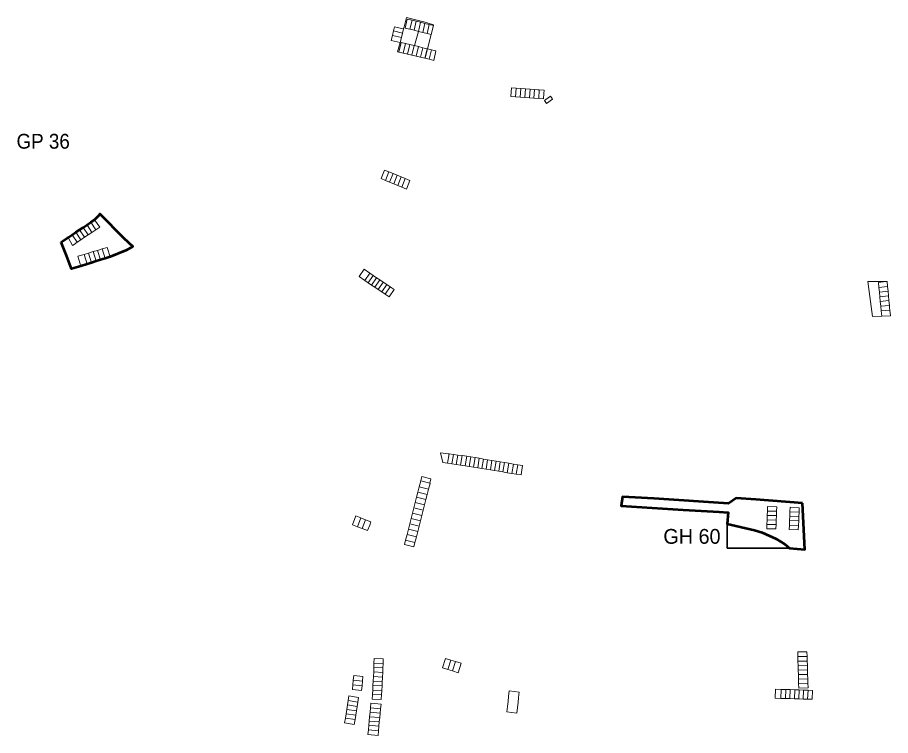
# Model space of a CAD drawing. Extents: x -648438 to -645379, y -1072966 to -1066997.
# Drawn here: x -646934 to -646344, y -1071165 to -1070679 of the extents above; entities that cross this region are included whole.
import ezdxf

# ---------------------------------------------------------------- set-up
doc = ezdxf.new("R2010")
doc.units = 0
doc.header["$LTSCALE"] = 4
doc.layers.add('40', color=7, linetype='Continuous', lineweight=13)
doc.layers.add('60', color=7, linetype='Continuous', lineweight=53)
doc.layers.add('56', color=7, linetype='Continuous')

msp = doc.modelspace()

# ---------------------------------------------------------------- linework, layer by layer
at = {"layer": '40'}
for points in [[(-646677.35, -1070702.69), (-646675.73, -1070696.39), (-646674.86, -1070693), (-646674.11, -1070690.05), (-646673.39, -1070687.24), (-646673.24, -1070686.66), (-646671.4, -1070679.49), (-646659.58, -1070682.49), (-646653.11, -1070684.4), (-646653.22, -1070684.87), (-646655.99, -1070684.19), (-646658.95, -1070683.47), (-646661.87, -1070682.76), (-646664.73, -1070682.06), (-646667.6, -1070681.36), (-646670.86, -1070680.56), (-646672.35, -1070686.63), (-646669.06, -1070687.45), (-646666.2, -1070688.16), (-646663.34, -1070688.87), (-646666.02, -1070698.52), (-646666.17, -1070698.49), (-646669.09, -1070697.79), (-646672, -1070697.09), (-646675.08, -1070696.34), (-646676.65, -1070702.85)], [(-646672.35, -1070686.63), (-646670.86, -1070680.56), (-646667.6, -1070681.36), (-646669.06, -1070687.45)], [(-646669.06, -1070687.45), (-646667.6, -1070681.36), (-646664.73, -1070682.06), (-646666.2, -1070688.16)], [(-646666.2, -1070688.16), (-646664.73, -1070682.06), (-646661.87, -1070682.76), (-646663.34, -1070688.87)], [(-646680.1, -1070688.63), (-646679.41, -1070685.78), (-646673.63, -1070687.18), (-646673.48, -1070686.59), (-646673.24, -1070686.66), (-646673.39, -1070687.24), (-646674.11, -1070690.05)], [(-646663.34, -1070688.87), (-646661.87, -1070682.76), (-646658.95, -1070683.47), (-646660.43, -1070689.59)], [(-646660.43, -1070689.59), (-646658.95, -1070683.47), (-646655.99, -1070684.19), (-646657.47, -1070690.33)], [(-646657.47, -1070690.33), (-646655.99, -1070684.19), (-646653.22, -1070684.87), (-646654.7, -1070691.02)], [(-646681.63, -1070694.97), (-646680.81, -1070691.57), (-646674.86, -1070693), (-646675.73, -1070696.39)], [(-646680.81, -1070691.57), (-646680.1, -1070688.63), (-646674.11, -1070690.05), (-646674.86, -1070693)], [(-646666.02, -1070698.52), (-646663.34, -1070688.87), (-646660.43, -1070689.59), (-646657.47, -1070690.33), (-646654.7, -1070691.02), (-646657.18, -1070700.66), (-646657.42, -1070700.6), (-646660.34, -1070699.9), (-646663.26, -1070699.19)], [(-646676.65, -1070702.85), (-646675.08, -1070696.34), (-646672, -1070697.09), (-646673.57, -1070703.57)], [(-646673.57, -1070703.57), (-646672, -1070697.09), (-646669.09, -1070697.79), (-646670.64, -1070704.24), (-646671.31, -1070704.08)], [(-646670.64, -1070704.24), (-646669.09, -1070697.79), (-646666.17, -1070698.49), (-646667.72, -1070704.91)], [(-646667.72, -1070704.91), (-646666.17, -1070698.49), (-646666.02, -1070698.52), (-646663.26, -1070699.19), (-646664.8, -1070705.59)], [(-646664.8, -1070705.59), (-646663.26, -1070699.19), (-646660.34, -1070699.9), (-646661.87, -1070706.26)], [(-646661.87, -1070706.26), (-646660.34, -1070699.9), (-646657.42, -1070700.6), (-646658.95, -1070706.94)], [(-646658.77, -1070706.98), (-646657.18, -1070700.66), (-646654.51, -1070701.3), (-646656.04, -1070707.68)], [(-646656.04, -1070707.68), (-646654.51, -1070701.3), (-646651.44, -1070702.04), (-646652.99, -1070708.46)], [(-646600.9, -1070732.89), (-646600.51, -1070726.98), (-646597.22, -1070727.23), (-646597.61, -1070733.13)], [(-646597.61, -1070733.13), (-646597.22, -1070727.23), (-646594.02, -1070727.47), (-646594.47, -1070733.36)], [(-646594.47, -1070733.36), (-646594.02, -1070727.47), (-646590.93, -1070727.7), (-646591.33, -1070733.59)], [(-646591.33, -1070733.59), (-646590.93, -1070727.7), (-646587.89, -1070727.92), (-646588.28, -1070733.81)], [(-646588.28, -1070733.81), (-646587.89, -1070727.92), (-646584.85, -1070728.15), (-646585.24, -1070734.03)], [(-646585.24, -1070734.03), (-646584.85, -1070728.15), (-646582.7, -1070728.32), (-646581.66, -1070728.39), (-646582, -1070734.27)], [(-646582, -1070734.27), (-646581.66, -1070728.39), (-646578.36, -1070728.64), (-646578.52, -1070730.86), (-646578.79, -1070734.5)], [(-646578.16, -1070735.61), (-646574.77, -1070733.15), (-646574.08, -1070732.65), (-646572.92, -1070734.27), (-646572.63, -1070734.68), (-646576.69, -1070737.66)], [(-646688.61, -1070788.33), (-646686.28, -1070782.59), (-646683.23, -1070783.84), (-646685.59, -1070789.58)], [(-646685.59, -1070789.58), (-646683.23, -1070783.84), (-646680.46, -1070784.99), (-646682.82, -1070790.72)], [(-646682.82, -1070790.72), (-646680.46, -1070784.99), (-646677.68, -1070786.13), (-646680.04, -1070791.86)], [(-646680.04, -1070791.86), (-646677.68, -1070786.13), (-646674.91, -1070787.27), (-646677.27, -1070793)], [(-646677.27, -1070793), (-646674.91, -1070787.27), (-646672.18, -1070788.4), (-646674.54, -1070794.13)], [(-646674.54, -1070794.13), (-646672.18, -1070788.4), (-646669.04, -1070789.69), (-646671.4, -1070795.42)], [(-646884.68, -1070817.87), (-646882.18, -1070816.21), (-646878.76, -1070821.15), (-646881.4, -1070822.94)], [(-646894.84, -1070824.62), (-646892.34, -1070822.96), (-646888.92, -1070828.04), (-646891.39, -1070829.71)], [(-646892.34, -1070822.96), (-646889.85, -1070821.3), (-646886.45, -1070826.36), (-646888.92, -1070828.04)], [(-646889.85, -1070821.3), (-646887.3, -1070819.61), (-646883.98, -1070824.68), (-646886.45, -1070826.36)], [(-646887.3, -1070819.61), (-646884.68, -1070817.87), (-646881.4, -1070822.94), (-646883.98, -1070824.68)], [(-646900.09, -1070828.1), (-646897.34, -1070826.28), (-646893.87, -1070831.39), (-646896.07, -1070832.89), (-646897.11, -1070833.59)], [(-646897.34, -1070826.28), (-646894.84, -1070824.62), (-646891.39, -1070829.71), (-646893.87, -1070831.39)], [(-646877.01, -1070835.86), (-646873.81, -1070834.89), (-646871.78, -1070841.33), (-646875.05, -1070842.32)], [(-646893.56, -1070840.88), (-646889.31, -1070839.59), (-646887.32, -1070846.14), (-646891.42, -1070847.44)], [(-646889.31, -1070839.59), (-646886.25, -1070838.66), (-646884.27, -1070845.17), (-646887.32, -1070846.14)], [(-646886.25, -1070838.66), (-646883.09, -1070837.7), (-646881.11, -1070844.21), (-646884.27, -1070845.17)], [(-646883.09, -1070837.7), (-646880.22, -1070836.83), (-646878.26, -1070843.29), (-646881.11, -1070844.21)], [(-646880.22, -1070836.83), (-646877.01, -1070835.86), (-646875.05, -1070842.32), (-646878.26, -1070843.29)], [(-646703.35, -1070854.57), (-646700.07, -1070849.65), (-646696.2, -1070852.25), (-646699.54, -1070857.23)], [(-646699.54, -1070857.23), (-646696.2, -1070852.25), (-646693.87, -1070853.81), (-646697.21, -1070858.8)], [(-646697.21, -1070858.8), (-646693.87, -1070853.81), (-646691.63, -1070855.31), (-646694.97, -1070860.3)], [(-646694.97, -1070860.3), (-646691.63, -1070855.31), (-646689.39, -1070856.82), (-646692.73, -1070861.8)], [(-646692.73, -1070861.8), (-646689.39, -1070856.82), (-646687.15, -1070858.32), (-646690.49, -1070863.31)], [(-646690.49, -1070863.31), (-646687.15, -1070858.32), (-646684.66, -1070859.99), (-646688, -1070864.98)], [(-646359.49, -1070857.84), (-646347.32, -1070857.98), (-646352.44, -1070858.51), (-646352.1, -1070861.89), (-646351.77, -1070865.07), (-646351.44, -1070868.25), (-646351.11, -1070871.44), (-646350.78, -1070874.62), (-646350.45, -1070877.8), (-646350.1, -1070881.27), (-646356.37, -1070881.56)], [(-646352.44, -1070858.51), (-646347.32, -1070857.98), (-646346.58, -1070857.9), (-646346.23, -1070861.28), (-646352.1, -1070861.89)], [(-646688, -1070864.98), (-646684.66, -1070859.99), (-646682.41, -1070861.5), (-646685.76, -1070866.48)], [(-646685.76, -1070866.48), (-646682.41, -1070861.5), (-646679.78, -1070863.26), (-646683.12, -1070868.25)], [(-646352.1, -1070861.89), (-646346.23, -1070861.28), (-646345.9, -1070864.47), (-646351.77, -1070865.07)], [(-646351.77, -1070865.07), (-646345.9, -1070864.47), (-646345.57, -1070867.65), (-646351.44, -1070868.25)], [(-646351.44, -1070868.25), (-646345.57, -1070867.65), (-646345.25, -1070870.83), (-646351.11, -1070871.44)], [(-646351.11, -1070871.44), (-646345.25, -1070870.83), (-646344.92, -1070874.01), (-646350.78, -1070874.62)], [(-646350.78, -1070874.62), (-646344.92, -1070874.01), (-646344.79, -1070875.43), (-646344.59, -1070877.2), (-646350.45, -1070877.8)], [(-646350.45, -1070877.8), (-646344.59, -1070877.2), (-646344.2, -1070881.01), (-646344.47, -1070881.02), (-646350.1, -1070881.27)], [(-646648.46, -1070973.63), (-646643.2, -1070974.31), (-646642.58, -1070974.39), (-646643.77, -1070980.58), (-646646.72, -1070980.14)], [(-646643.77, -1070980.58), (-646642.58, -1070974.39), (-646639.61, -1070974.78), (-646640.81, -1070981.03)], [(-646640.81, -1070981.03), (-646639.61, -1070974.78), (-646636.68, -1070975.17), (-646637.89, -1070981.47)], [(-646637.89, -1070981.47), (-646636.68, -1070975.17), (-646633.76, -1070975.55), (-646634.97, -1070981.91)], [(-646634.97, -1070981.91), (-646633.76, -1070975.55), (-646630.58, -1070975.96), (-646631.81, -1070982.39)], [(-646631.81, -1070982.39), (-646630.58, -1070975.96), (-646627.81, -1070976.43), (-646628.91, -1070982.87)], [(-646628.91, -1070982.87), (-646627.81, -1070976.43), (-646625.05, -1070976.89), (-646626.1, -1070983.33)], [(-646626.1, -1070983.33), (-646625.05, -1070976.89), (-646622.27, -1070977.35), (-646623.24, -1070983.8)], [(-646623.24, -1070983.8), (-646622.27, -1070977.35), (-646619.33, -1070977.85), (-646620.38, -1070984.27)], [(-646620.38, -1070984.27), (-646619.33, -1070977.85), (-646616.52, -1070978.32), (-646617.57, -1070984.73)], [(-646617.57, -1070984.73), (-646616.52, -1070978.32), (-646613.7, -1070978.79), (-646614.7, -1070985.2)], [(-646614.7, -1070985.2), (-646613.7, -1070978.79), (-646610.85, -1070979.27), (-646611.84, -1070985.67)], [(-646611.84, -1070985.67), (-646610.85, -1070979.27), (-646607.98, -1070979.75), (-646608.98, -1070986.14)], [(-646608.98, -1070986.14), (-646607.98, -1070979.75), (-646605.22, -1070980.21), (-646606.22, -1070986.59)], [(-646606.22, -1070986.59), (-646605.22, -1070980.21), (-646602.31, -1070980.7), (-646603.31, -1070987.07)], [(-646603.31, -1070987.07), (-646602.31, -1070980.7), (-646599.16, -1070981.23), (-646600.15, -1070987.59)], [(-646600.15, -1070987.59), (-646599.16, -1070981.23), (-646596.2, -1070981.73), (-646597.19, -1070988.08)], [(-646597.19, -1070988.08), (-646596.2, -1070981.73), (-646592.99, -1070982.26), (-646593.93, -1070988.61)], [(-646662.72, -1070996.67), (-646661.69, -1070992.68), (-646655.69, -1070994.23), (-646655.4, -1070994.31), (-646656.43, -1070998.29)], [(-646661.69, -1070992.68), (-646660.9, -1070989.63), (-646654.9, -1070991.18), (-646655.69, -1070994.23)], [(-646664.51, -1071003.59), (-646663.62, -1071000.15), (-646657.33, -1071001.77), (-646658.21, -1071005.21)], [(-646663.62, -1071000.15), (-646662.72, -1070996.67), (-646656.43, -1070998.29), (-646657.33, -1071001.77)], [(-646665.42, -1071007.11), (-646664.51, -1071003.59), (-646658.21, -1071005.21), (-646659.12, -1071008.74)], [(-646667.31, -1071014.46), (-646666.39, -1071010.88), (-646660.1, -1071012.5), (-646661.02, -1071016.09)], [(-646666.39, -1071010.88), (-646665.42, -1071007.11), (-646659.12, -1071008.74), (-646660.1, -1071012.5)], [(-646427.44, -1071012.97), (-646427.33, -1071009.86), (-646421.16, -1071010.08), (-646421.23, -1071013.01)], [(-646412.2, -1071013.48), (-646412.09, -1071010.44), (-646405.94, -1071010.73), (-646406.05, -1071013.68)], [(-646707.84, -1071022.2), (-646705.56, -1071016.33), (-646702.14, -1071017.68), (-646704.45, -1071023.54)], [(-646704.45, -1071023.54), (-646702.14, -1071017.68), (-646698.98, -1071018.92), (-646701.29, -1071024.78)], [(-646669.16, -1071021.6), (-646668.23, -1071018.01), (-646661.94, -1071019.64), (-646662.86, -1071023.22)], [(-646668.23, -1071018.01), (-646667.31, -1071014.46), (-646661.02, -1071016.09), (-646661.94, -1071019.64)], [(-646427.67, -1071019), (-646427.55, -1071015.99), (-646421.34, -1071016.02), (-646421.46, -1071019.04)], [(-646427.55, -1071015.99), (-646427.44, -1071012.97), (-646421.23, -1071013.01), (-646421.34, -1071016.02)], [(-646412.44, -1071019.48), (-646412.32, -1071016.49), (-646406.17, -1071016.69), (-646406.29, -1071019.68)], [(-646412.32, -1071016.49), (-646412.2, -1071013.48), (-646406.05, -1071013.68), (-646406.17, -1071016.69)], [(-646701.29, -1071024.78), (-646698.98, -1071018.92), (-646695.39, -1071020.34), (-646696.24, -1071022.48), (-646697.71, -1071026.2)], [(-646670.08, -1071025.18), (-646669.16, -1071021.6), (-646662.86, -1071023.22), (-646663.79, -1071026.81)], [(-646427.9, -1071025.03), (-646427.79, -1071022.02), (-646421.58, -1071022.05), (-646421.65, -1071025.07)], [(-646427.79, -1071022.02), (-646427.67, -1071019), (-646421.46, -1071019.04), (-646421.58, -1071022.05)], [(-646412.67, -1071025.49), (-646412.57, -1071022.49), (-646406.42, -1071022.74), (-646406.54, -1071025.68)], [(-646412.57, -1071022.49), (-646412.44, -1071019.48), (-646406.29, -1071019.68), (-646406.42, -1071022.74)], [(-646671.99, -1071032.57), (-646671, -1071028.72), (-646664.7, -1071030.35), (-646665.63, -1071034.15)], [(-646671, -1071028.72), (-646670.08, -1071025.18), (-646663.79, -1071026.81), (-646664.7, -1071030.35)], [(-646672.76, -1071035.57), (-646671.99, -1071032.57), (-646665.63, -1071034.15), (-646666.42, -1071037.21)], [(-646693.39, -1071115.79), (-646693.29, -1071112.55), (-646687.07, -1071112.75), (-646687.18, -1071116)], [(-646643.43, -1071119.99), (-646641.41, -1071113.68), (-646644.98, -1071112.55), (-646647.02, -1071118.86)], [(-646406.97, -1071108.2), (-646400.81, -1071108.09), (-646400.63, -1071111.17), (-646406.93, -1071111.37)], [(-646406.93, -1071111.37), (-646400.63, -1071111.17), (-646400.52, -1071114.31), (-646406.82, -1071114.52)], [(-646693.54, -1071121.72), (-646693.38, -1071118.57), (-646687.27, -1071118.9), (-646687.44, -1071122.04)], [(-646693.39, -1071115.79), (-646687.18, -1071116), (-646687.13, -1071116.19), (-646687.27, -1071118.9), (-646693.38, -1071118.57)], [(-646640.21, -1071121.01), (-646638.21, -1071114.69), (-646641.41, -1071113.68), (-646643.43, -1071119.99)], [(-646636.35, -1071122.22), (-646634.44, -1071115.83), (-646638.21, -1071114.69), (-646640.21, -1071121.01)], [(-646406.82, -1071114.52), (-646400.52, -1071114.31), (-646400.43, -1071117.31), (-646406.72, -1071117.52)], [(-646406.72, -1071117.52), (-646400.43, -1071117.31), (-646400.33, -1071120.33), (-646406.62, -1071120.54)], [(-646707.32, -1071127.23), (-646707.05, -1071124.1), (-646700.81, -1071124.67), (-646701.12, -1071127.82)], [(-646693.71, -1071124.81), (-646693.54, -1071121.72), (-646687.44, -1071122.04), (-646687.61, -1071125.14)], [(-646406.62, -1071120.54), (-646400.33, -1071120.33), (-646400.23, -1071123.33), (-646406.52, -1071123.53)], [(-646406.52, -1071123.53), (-646400.23, -1071123.33), (-646400.13, -1071126.33), (-646406.43, -1071126.53)], [(-646707.91, -1071133.62), (-646707.64, -1071130.48), (-646701.4, -1071131.04), (-646701.68, -1071134.17)], [(-646707.64, -1071130.48), (-646707.32, -1071127.23), (-646701.12, -1071127.82), (-646701.4, -1071131.04)], [(-646694.02, -1071130.75), (-646693.87, -1071127.86), (-646687.77, -1071128.18), (-646687.93, -1071131.08)], [(-646693.87, -1071127.86), (-646693.71, -1071124.81), (-646687.61, -1071125.14), (-646687.53, -1071126.08), (-646687.77, -1071128.18)], [(-646406.43, -1071126.53), (-646400.13, -1071126.33), (-646400.03, -1071129.25), (-646406.33, -1071129.46)], [(-646406.33, -1071129.46), (-646400.03, -1071129.25), (-646399.93, -1071132.4), (-646406.23, -1071132.61)], [(-646694.35, -1071136.94), (-646694.19, -1071133.9), (-646688.1, -1071134.22), (-646688.26, -1071137.27)], [(-646694.19, -1071133.9), (-646694.02, -1071130.75), (-646687.93, -1071131.08), (-646688.1, -1071134.22)], [(-646603.53, -1071148.59), (-646603.13, -1071145.01), (-646602.75, -1071141.68), (-646602.36, -1071138.25), (-646601.97, -1071134.57), (-646595.24, -1071135.46), (-646595.56, -1071139.02), (-646595.94, -1071142.45), (-646596.32, -1071145.78), (-646596.74, -1071149.51)], [(-646422.28, -1071139.47), (-646422.05, -1071133.32), (-646418.17, -1071133.45), (-646418.45, -1071139.58)], [(-646418.45, -1071139.58), (-646418.17, -1071133.45), (-646414.95, -1071133.55), (-646415.23, -1071139.66)], [(-646415.23, -1071139.66), (-646414.95, -1071133.55), (-646411.95, -1071133.65), (-646412.23, -1071139.75)], [(-646412.23, -1071139.75), (-646411.95, -1071133.65), (-646408.95, -1071133.75), (-646409.22, -1071139.83)], [(-646409.22, -1071139.83), (-646408.95, -1071133.75), (-646406.19, -1071133.83), (-646405.95, -1071133.84), (-646406.23, -1071139.91)], [(-646406.23, -1071139.91), (-646405.95, -1071133.84), (-646402.98, -1071133.94), (-646403.26, -1071139.99)], [(-646403.26, -1071139.99), (-646402.98, -1071133.94), (-646399.98, -1071134.04), (-646400.26, -1071140.07)], [(-646400.26, -1071140.07), (-646399.98, -1071134.04), (-646396.86, -1071134.14), (-646397.14, -1071140.16)], [(-646711.29, -1071144), (-646710.83, -1071141.04), (-646704.31, -1071142.07), (-646704.77, -1071145.03)], [(-646710.83, -1071141.04), (-646710.32, -1071137.83), (-646703.8, -1071138.86), (-646704.31, -1071142.07)], [(-646694.52, -1071140.09), (-646694.35, -1071136.94), (-646688.26, -1071137.27), (-646688.47, -1071139.89), (-646688.43, -1071140.41)], [(-646712.23, -1071149.93), (-646711.76, -1071146.97), (-646705.24, -1071148), (-646705.71, -1071150.96)], [(-646711.76, -1071146.97), (-646711.29, -1071144), (-646704.77, -1071145.03), (-646705.24, -1071148)], [(-646696, -1071148.98), (-646695.72, -1071146), (-646688.9, -1071146.64), (-646689.18, -1071149.63)], [(-646695.72, -1071146), (-646695.41, -1071142.79), (-646688.59, -1071143.43), (-646688.9, -1071146.64)], [(-646713.23, -1071156.1), (-646712.7, -1071152.89), (-646706.18, -1071153.92), (-646706.69, -1071157.13)], [(-646712.7, -1071152.89), (-646712.23, -1071149.93), (-646705.71, -1071150.96), (-646706.18, -1071153.92)], [(-646696.56, -1071154.86), (-646696.28, -1071151.92), (-646689.46, -1071152.56), (-646689.74, -1071155.5)], [(-646696.28, -1071151.92), (-646696, -1071148.98), (-646689.18, -1071149.63), (-646689.46, -1071152.56)], [(-646697.12, -1071160.78), (-646696.83, -1071157.74), (-646690.01, -1071158.39), (-646690.3, -1071161.42)], [(-646696.83, -1071157.74), (-646696.56, -1071154.86), (-646689.74, -1071155.5), (-646690.01, -1071158.39)], [(-646697.42, -1071164.01), (-646697.12, -1071160.78), (-646690.3, -1071161.42), (-646690.6, -1071164.66)]]:
    msp.add_lwpolyline(points, close=True, dxfattribs=at)
at = {"layer": '40', "lineweight": 35}
msp.add_lwpolyline([(-646454.59, -1071021.54), (-646454.59, -1071038), (-646412.54, -1071038.01), (-646415.61, -1071035.4), (-646421.58, -1071031.81), (-646430.91, -1071027.44)], close=True, dxfattribs=at)
at = {"layer": '60'}
for points in [[(-646904.8, -1070831.23), (-646900.57, -1070828.42), (-646900.09, -1070828.1), (-646897.34, -1070826.28), (-646894.84, -1070824.62), (-646892.34, -1070822.96), (-646889.85, -1070821.3), (-646887.3, -1070819.61), (-646884.68, -1070817.87), (-646882.18, -1070816.21), (-646878.66, -1070812.72), (-646878.61, -1070812.14), (-646862.56, -1070828.29), (-646856.41, -1070834.13), (-646860.55, -1070836.71), (-646871.78, -1070841.33), (-646875.05, -1070842.32), (-646878.26, -1070843.29), (-646881.11, -1070844.21), (-646884.27, -1070845.17), (-646887.32, -1070846.14), (-646891.42, -1070847.44), (-646897.71, -1070849.39), (-646901.26, -1070840.31)], [(-646403.81, -1071007.7), (-646435.28, -1071005.2), (-646448.48, -1071004.25), (-646453.7, -1071007.79), (-646504.25, -1071004.54), (-646516.78, -1071003.78), (-646525.4, -1071003.29), (-646526.31, -1071009.55), (-646484.27, -1071012.11), (-646460.09, -1071013.61), (-646454.02, -1071013.98), (-646454.59, -1071021.54), (-646436.15, -1071025.97), (-646430.91, -1071027.44), (-646421.58, -1071031.81), (-646415.61, -1071035.4), (-646412.54, -1071038.01), (-646402.09, -1071038.95)]]:
    msp.add_lwpolyline(points, close=True, dxfattribs=at)

# ---------------------------------------------------------------- texts
at = {"layer": '56', "width": 0.95}
msp.add_text('GP 36', height=10, dxfattribs=at).set_placement((-646934.974, -1070768.131))
at = {"layer": '56'}
msp.add_text('GH 60', height=10, dxfattribs=at).set_placement((-646497.751, -1071035.096))

doc.saveas('drawing.dxf')
